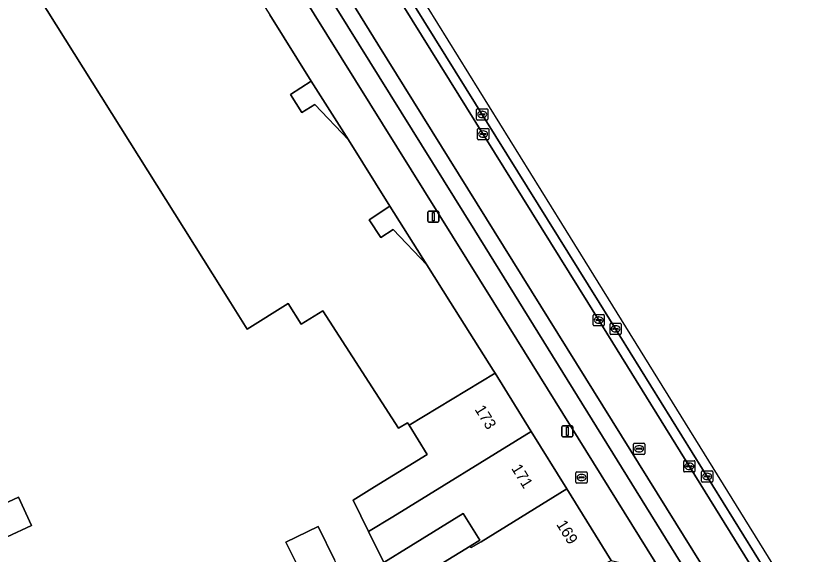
# Model space of a CAD drawing. Extents: x 159888 to 160761, y 384031 to 384750.
# Drawn here: x 160625.8 to 160696, y 384227.5 to 384275.6 of the extents above; entities that cross this region are included whole.
import ezdxf

# ---------------------------------------------------------------- set-up
doc = ezdxf.new("R2010")
doc.units = 0
for name, color, linetype in [('IMGEO_Berm_open', 7, 'Continuous'), ('IMGEO_Brandkraan', 7, 'Continuous'), ('IMGEO_Erf', 7, 'Continuous'), ('IMGEO_Kolk', 7, 'Continuous'), ('IMGEO_Lichtmast', 7, 'Continuous'), ('IMGEO_Pand', 7, 'Continuous'), ('IMGEO_Pand_nummerreeks', 7, 'Continuous'), ('IMGEO_Pand_overbouw', 7, 'Continuous'), ('IMGEO_Parkeervlak_gesloten', 7, 'Continuous'), ('IMGEO_Rijbaan_lokaal_gesloten', 7, 'Continuous'), ('IMGEO_Rioolput', 7, 'Continuous'), ('IMGEO_Voetpad_open', 7, 'Continuous')]:
    doc.layers.add(name, color=color, linetype=linetype)

msp = doc.modelspace()

# ---------------------------------------------------------------- linework, layer by layer
at = {"layer": 'IMGEO_Berm_open'}
msp.add_lwpolyline([(160632.074, 384323.722), (160631.369, 384323.299), (160676.893, 384250), (160716.199, 384186.525), (160720.54, 384179.603), (160721.392, 384178.231), (160722.103, 384178.75), (160721.789, 384179.196), (160717.593, 384185.942), (160677.924, 384250)], close=True, dxfattribs=at)
at = {"layer": 'IMGEO_Brandkraan'}
for p, q in [((160675.843, 384233.93), (160675.843, 384234.782)), ((160675.918, 384234.856), (160676.77, 384234.856)), ((160676.331, 384234.636), (160676.356, 384234.636)), ((160676.844, 384234.782), (160676.844, 384233.93)), ((160676.102, 384234.35), (160676.102, 384234.362)), ((160676.54, 384234.313), (160676.142, 384234.313)), ((160676.145, 384234.399), (160676.543, 384234.399)), ((160676.354, 384234.076), (160676.329, 384234.076)), ((160676.586, 384234.362), (160676.586, 384234.35)), ((160676.77, 384233.856), (160675.918, 384233.856))]:
    msp.add_line(p, q, dxfattribs=at)
for points in [[(160675.843, 384233.93), (160675.843, 384234.782)], [(160675.918, 384234.856), (160676.77, 384234.856)], [(160676.844, 384234.782), (160676.844, 384233.93)], [(160676.77, 384233.856), (160675.918, 384233.856)]]:
    msp.add_lwpolyline(points, dxfattribs=at)
for centre, radius, start, end in [((160675.92, 384234.78), 0.0765, 91.55205, 178.44795), ((160675.92, 384234.78), 0.0765, 91.55205, 178.44795), ((160676.768, 384234.78), 0.0765, 1.55205, 88.44795), ((160676.768, 384234.78), 0.0765, 1.55205, 88.44795), ((160675.92, 384233.932), 0.0765, 181.55205, 268.44795), ((160675.92, 384233.932), 0.0765, 181.55205, 268.44795), ((160676.142, 384234.359), 0.0403, 85.87752, 175.75265), ((160676.139, 384234.349), 0.0366, 178.93798, 274.71019), ((160676.543, 384234.356), 0.043, 264.86636, 352.45326), ((160676.547, 384234.361), 0.0386, 1.73085, 96.63898), ((160676.768, 384233.932), 0.0765, 271.55205, 358.44795), ((160676.768, 384233.932), 0.0765, 271.55205, 358.44795)]:
    msp.add_arc(centre, radius, start, end, dxfattribs=at)
for centre, major_axis, ratio, start_param, end_param in [((160676.33, 384234.356), (-0.387, 0.002), 0.722429, 4.712389, 7.853982), ((160676.355, 384234.356), (-0.39, 0.002), 0.717154, 1.570796, 4.712389)]:
    msp.add_ellipse(centre, major_axis=major_axis, ratio=ratio, start_param=start_param, end_param=end_param, dxfattribs=at)
at = {"layer": 'IMGEO_Erf'}
for points in [[(160664.014, 384226.75), (160666.399, 384228.221), (160667.25, 384228.746), (160665.782, 384231.126), (160661.104, 384228.241), (160658.685, 384226.749), (160657.328, 384229.515), (160655.945, 384232.335), (160657.853, 384233.512), (160662.545, 384236.406), (160660.934, 384239.017), (160660.794, 384239.243), (160660.004, 384238.756), (160653.231, 384249.261), (160651.308, 384248.05), (160650.15, 384249.904), (160646.485, 384247.599), (160644.978, 384250), (160614.619, 384298.372)], [(160651.091, 384226.236), (160649.946, 384228.562), (160652.809, 384229.978), (160654.283, 384226.998)]]:
    msp.add_lwpolyline(points, dxfattribs=at)
for points in [[(160652.188, 384269.772), (160650.353, 384268.572), (160651.352, 384266.979), (160652.515, 384267.706), (160655.532, 384264.527)], [(160659.234, 384258.591), (160657.378, 384257.39), (160658.408, 384255.798), (160659.524, 384256.52), (160662.536, 384253.347)], [(160621.573, 384230.497), (160626.05, 384232.584), (160627.219, 384230.076), (160622.856, 384228.041)]]:
    msp.add_lwpolyline(points, close=True, dxfattribs=at)
at = {"layer": 'IMGEO_Kolk'}
for p, q in [((160666.969, 384266.38), (160666.969, 384267.232)), ((160667.044, 384267.306), (160667.896, 384267.306)), ((160667.457, 384267.086), (160667.482, 384267.086)), ((160667.97, 384267.232), (160667.97, 384266.38)), ((160667.896, 384266.306), (160667.044, 384266.306)), ((160667.228, 384266.8), (160667.228, 384266.812)), ((160667.666, 384266.763), (160667.268, 384266.763)), ((160667.271, 384266.849), (160667.669, 384266.849)), ((160667.48, 384266.526), (160667.455, 384266.526)), ((160667.712, 384266.812), (160667.712, 384266.8)), ((160667.052, 384264.622), (160667.052, 384265.474)), ((160667.127, 384265.548), (160667.979, 384265.548)), ((160668.053, 384265.474), (160668.053, 384264.622)), ((160667.311, 384265.042), (160667.311, 384265.054)), ((160667.749, 384265.005), (160667.351, 384265.005)), ((160667.354, 384265.091), (160667.752, 384265.091)), ((160667.54, 384265.328), (160667.565, 384265.328)), ((160667.795, 384265.054), (160667.795, 384265.042)), ((160667.979, 384264.548), (160667.127, 384264.548)), ((160667.563, 384264.768), (160667.538, 384264.768)), ((160677.371, 384247.995), (160677.371, 384248.847)), ((160677.446, 384248.921), (160678.298, 384248.921)), ((160677.859, 384248.701), (160677.884, 384248.701)), ((160678.372, 384248.847), (160678.372, 384247.995)), ((160677.63, 384248.415), (160677.63, 384248.427)), ((160678.068, 384248.378), (160677.67, 384248.378)), ((160677.673, 384248.464), (160678.071, 384248.464)), ((160677.882, 384248.141), (160677.857, 384248.141)), ((160678.114, 384248.427), (160678.114, 384248.415)), ((160678.882, 384247.215), (160678.882, 384248.067)), ((160678.957, 384248.141), (160679.809, 384248.141)), ((160679.883, 384248.067), (160679.883, 384247.215)), ((160678.298, 384247.921), (160677.446, 384247.921)), ((160679.141, 384247.635), (160679.141, 384247.647)), ((160679.579, 384247.598), (160679.181, 384247.598)), ((160679.184, 384247.684), (160679.582, 384247.684)), ((160679.393, 384247.361), (160679.368, 384247.361)), ((160679.37, 384247.921), (160679.395, 384247.921)), ((160679.625, 384247.647), (160679.625, 384247.635)), ((160679.809, 384247.141), (160678.957, 384247.141)), ((160685.464, 384234.926), (160685.464, 384235.778)), ((160685.539, 384235.852), (160686.391, 384235.852)), ((160685.723, 384235.346), (160685.723, 384235.358)), ((160686.161, 384235.309), (160685.763, 384235.309)), ((160685.766, 384235.395), (160686.164, 384235.395)), ((160685.952, 384235.632), (160685.977, 384235.632)), ((160686.207, 384235.358), (160686.207, 384235.346)), ((160686.465, 384235.778), (160686.465, 384234.926)), ((160686.391, 384234.852), (160685.539, 384234.852)), ((160685.975, 384235.072), (160685.95, 384235.072)), ((160687.052, 384234.022), (160687.052, 384234.874)), ((160687.127, 384234.948), (160687.979, 384234.948)), ((160687.54, 384234.728), (160687.565, 384234.728)), ((160688.053, 384234.874), (160688.053, 384234.022)), ((160687.979, 384233.948), (160687.127, 384233.948)), ((160687.311, 384234.442), (160687.311, 384234.454)), ((160687.749, 384234.405), (160687.351, 384234.405)), ((160687.354, 384234.491), (160687.752, 384234.491)), ((160687.563, 384234.168), (160687.538, 384234.168)), ((160687.795, 384234.454), (160687.795, 384234.442))]:
    msp.add_line(p, q, dxfattribs=at)
for points in [[(160666.969, 384266.38), (160666.969, 384267.232)], [(160667.044, 384267.306), (160667.896, 384267.306)], [(160667.97, 384267.232), (160667.97, 384266.38)], [(160667.896, 384266.306), (160667.044, 384266.306)], [(160667.052, 384264.622), (160667.052, 384265.474)], [(160667.127, 384265.548), (160667.979, 384265.548)], [(160668.053, 384265.474), (160668.053, 384264.622)], [(160667.979, 384264.548), (160667.127, 384264.548)], [(160677.371, 384247.995), (160677.371, 384248.847)], [(160677.446, 384248.921), (160678.298, 384248.921)], [(160678.372, 384248.847), (160678.372, 384247.995)], [(160678.882, 384247.215), (160678.882, 384248.067)], [(160678.957, 384248.141), (160679.809, 384248.141)], [(160679.883, 384248.067), (160679.883, 384247.215)], [(160678.298, 384247.921), (160677.446, 384247.921)], [(160679.809, 384247.141), (160678.957, 384247.141)], [(160685.464, 384234.926), (160685.464, 384235.778)], [(160685.539, 384235.852), (160686.391, 384235.852)], [(160686.465, 384235.778), (160686.465, 384234.926)], [(160686.391, 384234.852), (160685.539, 384234.852)], [(160687.052, 384234.022), (160687.052, 384234.874)], [(160687.127, 384234.948), (160687.979, 384234.948)], [(160688.053, 384234.874), (160688.053, 384234.022)], [(160687.979, 384233.948), (160687.127, 384233.948)]]:
    msp.add_lwpolyline(points, dxfattribs=at)
for centre, radius, start, end in [((160667.046, 384267.23), 0.0765, 91.55205, 178.44795), ((160667.046, 384267.23), 0.0765, 91.55205, 178.44795), ((160667.894, 384267.23), 0.0765, 1.55205, 88.44795), ((160667.894, 384267.23), 0.0765, 1.55205, 88.44795), ((160667.046, 384266.382), 0.0765, 181.55205, 268.44795), ((160667.046, 384266.382), 0.0765, 181.55205, 268.44795), ((160667.268, 384266.809), 0.0403, 85.87752, 175.75265), ((160667.265, 384266.799), 0.0366, 178.93798, 274.71019), ((160667.669, 384266.806), 0.043, 264.86636, 352.45326), ((160667.673, 384266.811), 0.0386, 1.73085, 96.63898), ((160667.894, 384266.382), 0.0765, 271.55205, 358.44795), ((160667.894, 384266.382), 0.0765, 271.55205, 358.44795), ((160667.129, 384265.472), 0.0765, 91.55205, 178.44795), ((160667.129, 384265.472), 0.0765, 91.55205, 178.44795), ((160667.977, 384265.472), 0.0765, 1.55205, 88.44795), ((160667.977, 384265.472), 0.0765, 1.55205, 88.44795), ((160667.351, 384265.051), 0.0403, 85.87752, 175.75265), ((160667.348, 384265.041), 0.0366, 178.93798, 274.71019), ((160667.752, 384265.048), 0.043, 264.86636, 352.45326), ((160667.756, 384265.053), 0.0386, 1.73085, 96.63898), ((160667.129, 384264.624), 0.0765, 181.55205, 268.44795), ((160667.129, 384264.624), 0.0765, 181.55205, 268.44795), ((160667.977, 384264.624), 0.0765, 271.55205, 358.44795), ((160667.977, 384264.624), 0.0765, 271.55205, 358.44795), ((160677.448, 384248.845), 0.0765, 91.55205, 178.44795), ((160677.448, 384248.845), 0.0765, 91.55205, 178.44795), ((160678.296, 384248.845), 0.0765, 1.55205, 88.44795), ((160678.296, 384248.845), 0.0765, 1.55205, 88.44795), ((160677.448, 384247.997), 0.0765, 181.55205, 268.44795), ((160677.448, 384247.997), 0.0765, 181.55205, 268.44795), ((160677.67, 384248.424), 0.0403, 85.87752, 175.75265), ((160677.667, 384248.414), 0.0366, 178.93798, 274.71019), ((160678.071, 384248.421), 0.043, 264.86636, 352.45326), ((160678.075, 384248.426), 0.0386, 1.73085, 96.63898), ((160678.296, 384247.997), 0.0765, 271.55205, 358.44795), ((160678.296, 384247.997), 0.0765, 271.55205, 358.44795), ((160678.959, 384248.065), 0.0765, 91.55205, 178.44795), ((160678.959, 384248.065), 0.0765, 91.55205, 178.44795), ((160679.807, 384248.065), 0.0765, 1.55205, 88.44795), ((160679.807, 384248.065), 0.0765, 1.55205, 88.44795), ((160679.181, 384247.644), 0.0403, 85.87752, 175.75265), ((160679.178, 384247.634), 0.0366, 178.93798, 274.71019), ((160679.582, 384247.641), 0.043, 264.86636, 352.45326), ((160679.586, 384247.646), 0.0386, 1.73085, 96.63898), ((160678.959, 384247.217), 0.0765, 181.55205, 268.44795), ((160678.959, 384247.217), 0.0765, 181.55205, 268.44795), ((160679.807, 384247.217), 0.0765, 271.55205, 358.44795), ((160679.807, 384247.217), 0.0765, 271.55205, 358.44795), ((160685.541, 384235.776), 0.0765, 91.55205, 178.44795), ((160685.541, 384235.776), 0.0765, 91.55205, 178.44795), ((160685.763, 384235.355), 0.0403, 85.87752, 175.75265), ((160685.76, 384235.345), 0.0366, 178.93798, 274.71019), ((160686.164, 384235.352), 0.043, 264.86636, 352.45326), ((160686.168, 384235.357), 0.0386, 1.73085, 96.63898), ((160686.389, 384235.776), 0.0765, 1.55205, 88.44795), ((160686.389, 384235.776), 0.0765, 1.55205, 88.44795), ((160685.541, 384234.928), 0.0765, 181.55205, 268.44795), ((160685.541, 384234.928), 0.0765, 181.55205, 268.44795), ((160686.389, 384234.928), 0.0765, 271.55205, 358.44795), ((160686.389, 384234.928), 0.0765, 271.55205, 358.44795), ((160687.129, 384234.872), 0.0765, 91.55205, 178.44795), ((160687.129, 384234.872), 0.0765, 91.55205, 178.44795), ((160687.977, 384234.872), 0.0765, 1.55205, 88.44795), ((160687.977, 384234.872), 0.0765, 1.55205, 88.44795), ((160687.129, 384234.024), 0.0765, 181.55205, 268.44795), ((160687.129, 384234.024), 0.0765, 181.55205, 268.44795), ((160687.351, 384234.451), 0.0403, 85.87752, 175.75265), ((160687.348, 384234.441), 0.0366, 178.93798, 274.71019), ((160687.752, 384234.448), 0.043, 264.86636, 352.45326), ((160687.756, 384234.453), 0.0386, 1.73085, 96.63898), ((160687.977, 384234.024), 0.0765, 271.55205, 358.44795), ((160687.977, 384234.024), 0.0765, 271.55205, 358.44795)]:
    msp.add_arc(centre, radius, start, end, dxfattribs=at)
for centre, major_axis, ratio, start_param, end_param in [((160667.456, 384266.806), (-0.387, 0.002), 0.722429, 4.712389, 7.853982), ((160667.481, 384266.806), (-0.39, 0.002), 0.717154, 1.570796, 4.712389), ((160667.539, 384265.048), (-0.387, 0.002), 0.722429, 4.712389, 7.853982), ((160667.564, 384265.048), (-0.39, 0.002), 0.717154, 1.570796, 4.712389), ((160677.858, 384248.421), (-0.387, 0.002), 0.722429, 4.712389, 7.853982), ((160677.883, 384248.421), (-0.39, 0.002), 0.717154, 1.570796, 4.712389), ((160679.369, 384247.641), (-0.387, 0.002), 0.722429, 4.712389, 7.853982), ((160679.394, 384247.641), (-0.39, 0.002), 0.717154, 1.570796, 4.712389), ((160685.951, 384235.352), (-0.387, 0.002), 0.722429, 4.712389, 7.853982), ((160685.976, 384235.352), (-0.39, 0.002), 0.717154, 1.570796, 4.712389), ((160687.539, 384234.448), (-0.387, 0.002), 0.722429, 4.712389, 7.853982), ((160687.564, 384234.448), (-0.39, 0.002), 0.717154, 1.570796, 4.712389)]:
    msp.add_ellipse(centre, major_axis=major_axis, ratio=ratio, start_param=start_param, end_param=end_param, dxfattribs=at)
at = {"layer": 'IMGEO_Lichtmast'}
for p, q in [((160662.615, 384257.264), (160662.615, 384258.064)), ((160662.615, 384258.064), (160662.615, 384257.264)), ((160662.715, 384258.164), (160663.505, 384258.164)), ((160663.505, 384258.164), (160662.715, 384258.164)), ((160663.605, 384258.064), (160663.605, 384257.264)), ((160663.605, 384257.264), (160663.605, 384258.064)), ((160663.505, 384257.164), (160662.715, 384257.164)), ((160662.715, 384257.164), (160663.505, 384257.164)), ((160674.576, 384238.077), (160674.576, 384238.877)), ((160674.576, 384238.877), (160674.576, 384238.077)), ((160674.676, 384238.977), (160675.466, 384238.977)), ((160675.466, 384238.977), (160674.676, 384238.977)), ((160675.566, 384238.877), (160675.566, 384238.077)), ((160675.566, 384238.077), (160675.566, 384238.877)), ((160675.466, 384237.977), (160674.676, 384237.977)), ((160674.676, 384237.977), (160675.466, 384237.977))]:
    msp.add_line(p, q, dxfattribs=at)
for points in [[(160663.035, 384258.039), (160663.185, 384258.039), (160663.185, 384257.289), (160663.035, 384257.289), (160663.035, 384258.039)], [(160674.996, 384238.852), (160675.146, 384238.852), (160675.146, 384238.102), (160674.996, 384238.102), (160674.996, 384238.852)]]:
    msp.add_lwpolyline(points, dxfattribs=at)
for centre, start, end in [((160662.715, 384258.064), 90, 180), ((160662.715, 384258.064), 90, 180), ((160663.505, 384258.064), 0, 90), ((160663.505, 384258.064), 360, 90), ((160662.715, 384257.264), 180, 270), ((160662.715, 384257.264), 180, 270), ((160663.505, 384257.264), 270, 0), ((160663.505, 384257.264), 270, 0), ((160674.676, 384238.877), 90, 180), ((160674.676, 384238.877), 90, 180), ((160675.466, 384238.877), 0, 90), ((160675.466, 384238.877), 360, 90), ((160674.676, 384238.077), 180, 270), ((160674.676, 384238.077), 180, 270), ((160675.466, 384238.077), 270, 0), ((160675.466, 384238.077), 270, 0)]:
    msp.add_arc(centre, 0.1, start, end, dxfattribs=at)
at = {"layer": 'IMGEO_Pand'}
msp.add_lwpolyline([(160614.619, 384298.372), (160644.978, 384250), (160646.485, 384247.599), (160650.15, 384249.904), (160651.308, 384248.05), (160653.231, 384249.261), (160660.004, 384238.756), (160660.794, 384239.243), (160660.934, 384239.017), (160668.613, 384243.687), (160668.444, 384243.96), (160664.643, 384250), (160662.536, 384253.347), (160659.524, 384256.52), (160658.408, 384255.798), (160657.378, 384257.39), (160659.234, 384258.591), (160655.532, 384264.527), (160652.515, 384267.706), (160651.352, 384266.979), (160650.353, 384268.572), (160652.188, 384269.772), (160648.49, 384275.72)], dxfattribs=at)
for points in [[(160671.847, 384238.47), (160668.613, 384243.687), (160660.934, 384239.017), (160662.545, 384236.406), (160657.853, 384233.512), (160655.945, 384232.335), (160657.328, 384229.515), (160659.494, 384230.851)], [(160675.03, 384233.336), (160671.847, 384238.47), (160659.494, 384230.851), (160657.328, 384229.515), (160658.685, 384226.749), (160661.104, 384228.241), (160665.782, 384231.126), (160667.25, 384228.746), (160666.399, 384228.221), (160666.475, 384228.095), (160667.372, 384228.613)], [(160675.03, 384233.336), (160667.372, 384228.613), (160666.475, 384228.095), (160666.399, 384228.221), (160664.014, 384226.75), (160665.582, 384224.207), (160664.394, 384223.618), (160663.179, 384226.068), (160660.129, 384224.555), (160660.686, 384223.434), (160662.908, 384218.955), (160678.996, 384226.937)], [(160621.573, 384230.497), (160622.856, 384228.041), (160627.219, 384230.076), (160626.05, 384232.584)], [(160656.229, 384215.896), (160656.495, 384215.761), (160662.02, 384218.494), (160659.79, 384222.989), (160657.971, 384226.676), (160655.136, 384225.274), (160654.283, 384226.998), (160652.809, 384229.978), (160649.946, 384228.562), (160651.091, 384226.236)]]:
    msp.add_lwpolyline(points, close=True, dxfattribs=at)
at = {"layer": 'IMGEO_Pand_overbouw'}
for points in [[(160652.188, 384269.772), (160650.353, 384268.572), (160651.352, 384266.979), (160652.515, 384267.706), (160655.532, 384264.527)], [(160662.536, 384253.347), (160659.234, 384258.591), (160657.378, 384257.39), (160658.408, 384255.798), (160659.524, 384256.52)]]:
    msp.add_lwpolyline(points, close=True, dxfattribs=at)
at = {"layer": 'IMGEO_Parkeervlak_gesloten'}
msp.add_lwpolyline([(160627.201, 384320.153), (160626.898, 384320.642), (160624.721, 384324.154), (160623.028, 384323.095), (160625.204, 384319.595), (160668.501, 384250), (160682.874, 384226.85), (160687.066, 384220.06), (160690.34, 384214.758), (160703.28, 384193.928), (160705.339, 384190.616), (160709.635, 384183.701), (160711.54, 384180.634), (160712.528, 384179.044), (160725.705, 384157.813), (160717.699, 384173.243), (160713.185, 384181.538), (160666.822, 384256.425)], close=True, dxfattribs=at)
at = {"layer": 'IMGEO_Rijbaan_lokaal_gesloten'}
msp.add_lwpolyline([(160749.892, 384150.791), (160747.142, 384155.348), (160723.846, 384177.438), (160674.582, 384257.042), (160657.045, 384285.38), (160633.021, 384324.291), (160632.074, 384323.722), (160677.924, 384250), (160717.593, 384185.942), (160721.789, 384179.196), (160722.103, 384178.75)], dxfattribs=at)
for points in [[(160631.369, 384323.299), (160628.254, 384321.427), (160658.156, 384273.096), (160712.066, 384186.351), (160716.812, 384178.507), (160724.659, 384168.519), (160735.808, 384155.472), (160739.485, 384150.742), (160742.378, 384146.138), (160744.77, 384147.64), (160741.437, 384152.722), (160738.151, 384157.187), (160736.076, 384159.626), (160732.078, 384164.139), (160729.416, 384167.144), (160727.245, 384169.786), (160726.685, 384170.566), (160722.765, 384176.019), (160721.392, 384178.231), (160720.54, 384179.603), (160716.199, 384186.525), (160676.893, 384250)], [(160628.254, 384321.427), (160626.898, 384320.642), (160627.201, 384320.153), (160666.822, 384256.425), (160713.185, 384181.538), (160717.699, 384173.243), (160725.705, 384157.813), (160727.905, 384159.142), (160716.812, 384178.507), (160712.066, 384186.351), (160658.156, 384273.096)]]:
    msp.add_lwpolyline(points, close=True, dxfattribs=at)
at = {"layer": 'IMGEO_Rioolput'}
for p, q in [((160681.052, 384237.419), (160681.904, 384237.419)), ((160680.977, 384236.493), (160680.977, 384237.345)), ((160681.236, 384236.913), (160681.236, 384236.925)), ((160681.674, 384236.876), (160681.276, 384236.876)), ((160681.279, 384236.962), (160681.677, 384236.962)), ((160681.465, 384237.199), (160681.49, 384237.199)), ((160681.72, 384236.925), (160681.72, 384236.913)), ((160681.978, 384237.345), (160681.978, 384236.493)), ((160681.904, 384236.419), (160681.052, 384236.419)), ((160681.488, 384236.639), (160681.463, 384236.639))]:
    msp.add_line(p, q, dxfattribs=at)
for points in [[(160681.052, 384237.419), (160681.904, 384237.419)], [(160680.977, 384236.493), (160680.977, 384237.345)], [(160681.978, 384237.345), (160681.978, 384236.493)], [(160681.904, 384236.419), (160681.052, 384236.419)]]:
    msp.add_lwpolyline(points, dxfattribs=at)
for centre, radius, start, end in [((160681.054, 384237.343), 0.0765, 91.55205, 178.44795), ((160681.054, 384237.343), 0.0765, 91.55205, 178.44795), ((160681.902, 384237.343), 0.0765, 1.55205, 88.44795), ((160681.902, 384237.343), 0.0765, 1.55205, 88.44795), ((160681.276, 384236.922), 0.0403, 85.87752, 175.75265), ((160681.273, 384236.912), 0.0366, 178.93798, 274.71019), ((160681.677, 384236.919), 0.043, 264.86636, 352.45326), ((160681.681, 384236.924), 0.0386, 1.73085, 96.63898), ((160681.054, 384236.495), 0.0765, 181.55205, 268.44795), ((160681.054, 384236.495), 0.0765, 181.55205, 268.44795), ((160681.902, 384236.495), 0.0765, 271.55205, 358.44795), ((160681.902, 384236.495), 0.0765, 271.55205, 358.44795)]:
    msp.add_arc(centre, radius, start, end, dxfattribs=at)
for centre, major_axis, ratio, start_param, end_param in [((160681.464, 384236.919), (-0.387, 0.002), 0.722429, 4.712389, 7.853982), ((160681.489, 384236.919), (-0.39, 0.002), 0.717154, 1.570796, 4.712389)]:
    msp.add_ellipse(centre, major_axis=major_axis, ratio=ratio, start_param=start_param, end_param=end_param, dxfattribs=at)
at = {"layer": 'IMGEO_Voetpad_open'}
msp.add_lwpolyline([(160616.807, 384326.31), (160620.206, 384320.788), (160631.153, 384303.264), (160634.46, 384298.079), (160638.193, 384292.131), (160641.474, 384286.895), (160645.209, 384280.948), (160648.49, 384275.72), (160652.188, 384269.772), (160655.532, 384264.527), (160659.234, 384258.591), (160662.536, 384253.347), (160664.643, 384250), (160668.444, 384243.96), (160668.613, 384243.687), (160671.847, 384238.47), (160675.03, 384233.336), (160678.996, 384226.937), (160681.922, 384226.262), (160682.874, 384226.85), (160668.501, 384250), (160625.204, 384319.595)], dxfattribs=at)

# ---------------------------------------------------------------- texts
at = {"layer": 'IMGEO_Pand_nummerreeks'}
for s, rotation, p in [('173', 301.79322, (160666.764, 384240.445)), ('171', 301.79895, (160670.032, 384235.172)), ('169', 301.78999, (160674.051, 384230.17))]:
    msp.add_text(s, height=1, rotation=rotation, dxfattribs=at).set_placement(p)

doc.saveas('drawing.dxf')
